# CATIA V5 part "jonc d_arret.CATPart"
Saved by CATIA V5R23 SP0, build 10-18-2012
Part number: jonc d_arret
Definition: jonc d_arret
Source: bought
Bounding box of the stored display mesh (mm): x 192 to 196, y -14.943 to 15, z -15 to 15
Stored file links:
  C:\wamp\www\COURS\CONCEPTION GMP1\TITRE 01-CATIA VOLUMIQUE\05--ACTIONNEUR DE VANNE\prof\CORRECTION\Assemblage\jonc d_arret.CATPart
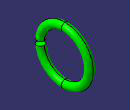
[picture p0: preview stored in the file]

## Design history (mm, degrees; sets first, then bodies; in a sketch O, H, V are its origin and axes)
Set1
  Plane1: type OffsetPt, RefPlane yz-plane, RefPoint {point type Center, Curve edge [face of Solid1 | face of Solid1]}
  Plane2: type Offset, RefPlane yz-plane, Offset 196
Body1 "NONE" (main body)
  Solid1 "Manifold Solid #2962": solid without history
